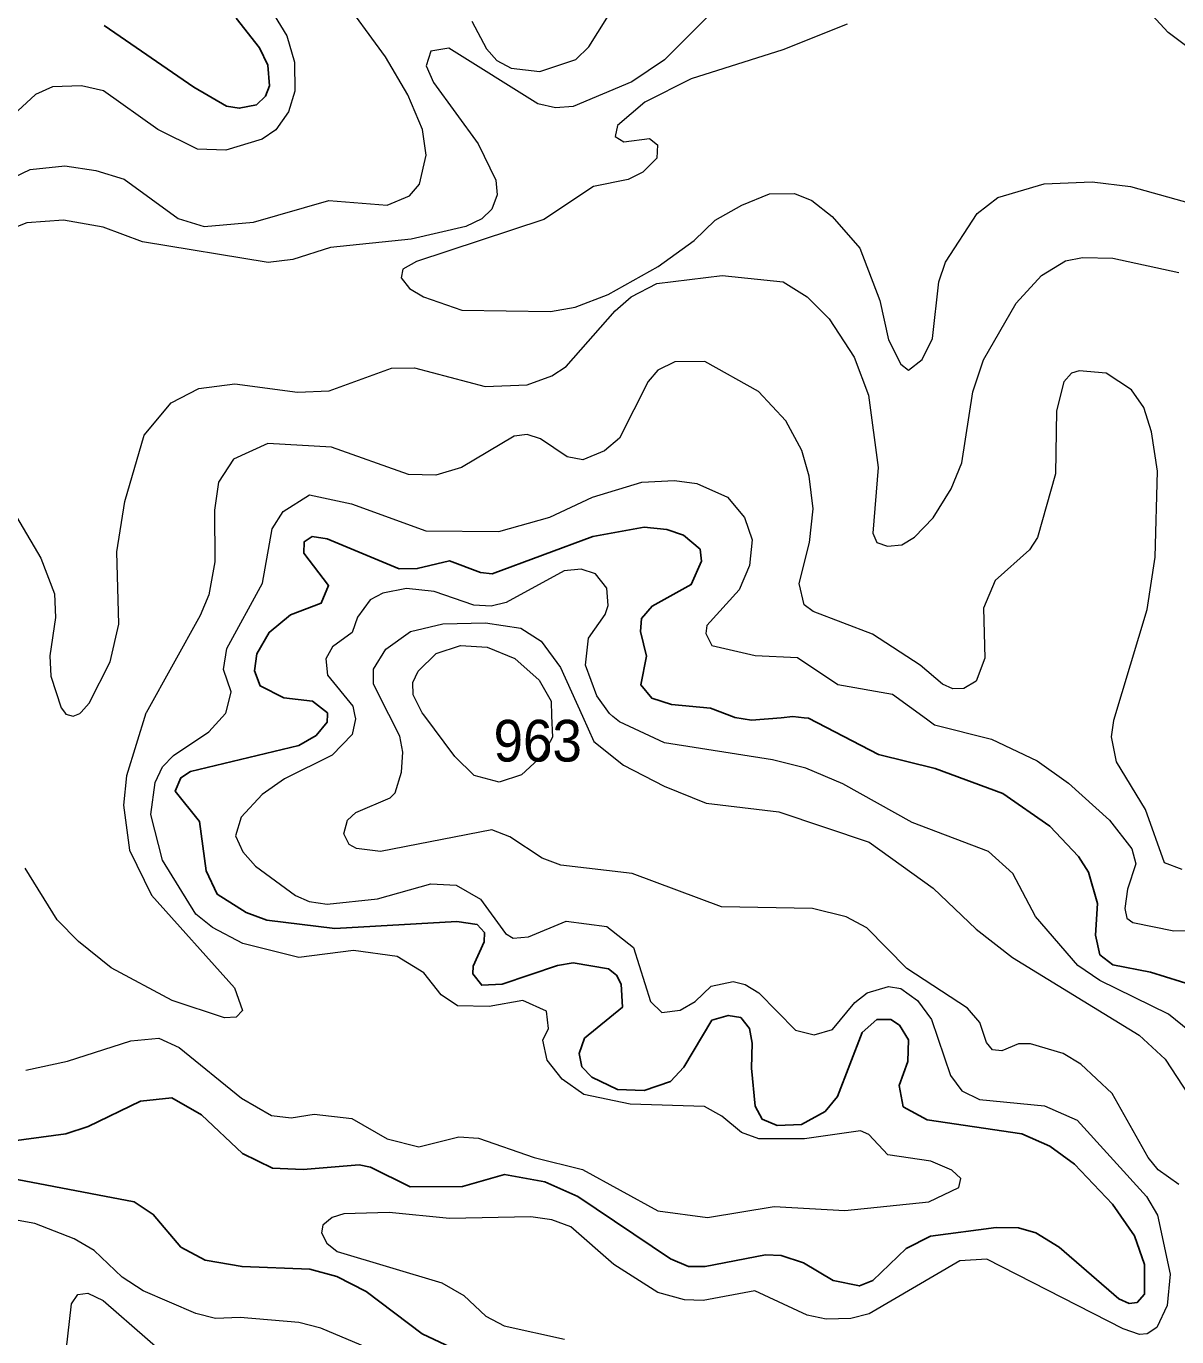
# Model space of a CAD drawing. Extents: x 473.9 to 500, y 7733.1 to 7760.8.
# Drawn here: x 487.667 to 489.876, y 7746.72 to 7749.235 of the extents above; entities that cross this region are included whole.
import ezdxf

# ---------------------------------------------------------------- set-up
doc = ezdxf.new("R2010")
doc.units = 0
doc.header["$LTSCALE"] = 0.032
doc.layers.add('1', color=7, linetype='Continuous', lineweight=25)
doc.layers.add('2', color=7, linetype='Continuous', lineweight=13)
doc.layers.add('21', color=7, linetype='Continuous')

msp = doc.modelspace()

# ---------------------------------------------------------------- linework, layer by layer
at = {"layer": '1'}
for points in [[(488.0704, 7749.25), (488.115, 7749.1932), (488.1315, 7749.16), (488.1344, 7749.1205), (488.1271, 7749.1005), (488.1098, 7749.084), (488.0764, 7749.0773), (488.052, 7749.0814), (487.9893, 7749.1176), (487.8171, 7749.2364)], [(488.2597, 7747.5034), (488.1295, 7747.5194), (488.09, 7747.5342), (488.0343, 7747.569), (488.0132, 7747.6137), (488.0001, 7747.7086), (487.9536, 7747.7668), (487.9642, 7747.7925), (487.9826, 7747.8046), (488.1908, 7747.8546), (488.2243, 7747.8739), (488.2451, 7747.899), (488.2455, 7747.9145), (488.2456, 7747.9168), (488.2167, 7747.9393), (488.1623, 7747.9461), (488.1163, 7747.9689), (488.1059, 7747.9974), (488.1101, 7748.0302), (488.134, 7748.0714), (488.1745, 7748.1053), (488.2338, 7748.1274), (488.2479, 7748.1614), (488.2003, 7748.2238), (488.2011, 7748.2455), (488.2166, 7748.2554), (488.2453, 7748.2511), (488.3836, 7748.1932), (488.4182, 7748.194), (488.4797, 7748.2087), (488.5398, 7748.1863), (488.5622, 7748.184), (488.755, 7748.2552), (488.8534, 7748.2732), (488.8974, 7748.2688), (488.9289, 7748.2583), (488.9614, 7748.2311), (488.9637, 7748.2083), (488.9441, 7748.1633), (488.8689, 7748.122), (488.8487, 7748.098), (488.8464, 7748.0734), (488.8584, 7748.0257), (488.8472, 7747.9706), (488.8683, 7747.945), (488.9064, 7747.9331), (488.9808, 7747.9259), (489.0262, 7747.9085), (489.0276, 7747.908), (489.0597, 7747.9028), (489.1168, 7747.9078), (489.139, 7747.9098), (489.1605, 7747.9075), (489.1689, 7747.9066), (489.3036, 7747.8372), (489.4123, 7747.8101), (489.5421, 7747.7621), (489.6326, 7747.6999), (489.6871, 7747.6415), (489.7064, 7747.6114), (489.7242, 7747.551), (489.7203, 7747.4905), (489.7286, 7747.4529), (489.7532, 7747.4337), (489.8256, 7747.4193), (489.9118, 7747.3922)], [(489.1596, 7746.8614), (489.2162, 7746.8274), (489.2669, 7746.8172), (489.2927, 7746.8277), (489.3563, 7746.8891), (489.403, 7746.913), (489.5291, 7746.9296), (489.5725, 7746.9289), (489.6057, 7746.9191), (489.6506, 7746.8915), (489.765, 7746.7922), (489.7848, 7746.7837), (489.8003, 7746.7855), (489.8143, 7746.8013), (489.814, 7746.8586), (489.7951, 7746.9133), (489.7525, 7746.9744), (489.6797, 7747.0507), (489.6324, 7747.0853), (489.5785, 7747.1088), (489.3968, 7747.1362), (489.3511, 7747.1612), (489.3432, 7747.2017), (489.3599, 7747.2481), (489.3608, 7747.2893), (489.3435, 7747.3174), (489.3269, 7747.3285), (489.3004, 7747.3288), (489.2721, 7747.3035), (489.225, 7747.1808), (489.2013, 7747.1522), (489.1554, 7747.1272), (489.1093, 7747.1248), (489.08, 7747.1373), (489.0669, 7747.1623), (489.0594, 7747.2352), (489.0613, 7747.2831), (489.056, 7747.3112), (489.0392, 7747.3322), (489.015, 7747.3364), (488.9836, 7747.3271), (488.9299, 7747.2369), (488.9041, 7747.2096), (488.8534, 7747.192), (488.8028, 7747.194), (488.7531, 7747.2176), (488.7342, 7747.238), (488.729, 7747.2636), (488.7391, 7747.2925), (488.8118, 7747.3519), (488.8097, 7747.3964), (488.8004, 7747.4136), (488.7853, 7747.4258), (488.7173, 7747.4372), (488.6872, 7747.4322), (488.5814, 7747.3965), (488.5419, 7747.3942), (488.5248, 7747.4165), (488.5255, 7747.4311), (488.5466, 7747.4777), (488.547, 7747.4957), (488.5331, 7747.5106), (488.4938, 7747.5166), (488.2597, 7747.5034)], [(487.6149, 7747.092), (487.7438, 7747.1092), (487.7866, 7747.1235), (487.8869, 7747.1719), (487.9468, 7747.1781), (488.004, 7747.1454), (488.0827, 7747.0713), (488.1405, 7747.0431), (488.1993, 7747.0407), (488.3066, 7747.0494), (488.3283, 7747.0449), (488.4042, 7747.0071), (488.5049, 7747.0082), (488.5858, 7747.031), (488.6627, 7747.0169), (488.7263, 7746.9888), (488.9043, 7746.8695), (488.9388, 7746.8542), (488.9705, 7746.8544), (489.0866, 7746.8766), (489.1167, 7746.8759), (489.1596, 7746.8614)], [(488.505, 7746.6889), (488.4277, 7746.725), (488.3199, 7746.8062), (488.2636, 7746.8351), (488.2121, 7746.8493), (488.0819, 7746.8542), (488.0107, 7746.8668), (487.9644, 7746.8914), (487.9112, 7746.9546), (487.8745, 7746.9789), (487.6368, 7747.0239)]]:
    msp.add_lwpolyline(points, dxfattribs=at)
at = {"layer": '2'}
for points in [[(490.0042, 7749.1272), (489.9516, 7749.1534), (489.8593, 7749.2228), (489.7146, 7749.381)], [(488.0844, 7749.3524), (488.1678, 7749.2162), (488.1823, 7749.166), (488.183, 7749.1102), (488.1708, 7749.0708), (488.1468, 7749.0362), (488.1206, 7749.0183), (488.0509, 7748.9967), (487.9961, 7748.9988), (487.9201, 7749.0363), (487.816, 7749.1107), (487.7737, 7749.1206), (487.7178, 7749.1184), (487.685, 7749.104), (487.6515, 7749.0725), (487.6157, 7749.0585), (487.4849, 7749.0582), (487.4608, 7749.0649), (487.3946, 7749.1045), (487.2779, 7749.2182), (487.2164, 7749.2396), (487.1231, 7749.2234), (487.0807, 7749.222), (486.9885, 7749.2429)], [(487.5798, 7748.9145), (487.6751, 7748.9597), (487.7416, 7748.967), (487.8011, 7748.9577), (487.8557, 7748.9412), (487.9589, 7748.8659), (488.009, 7748.8507), (488.1035, 7748.8588), (488.2481, 7748.9003), (488.3601, 7748.8912), (488.4032, 7748.9095), (488.4226, 7748.9318), (488.4354, 7748.9875), (488.428, 7749.0367), (488.4002, 7749.1032), (488.3574, 7749.1761), (488.2683, 7749.298)], [(488.523, 7749.2443), (488.5511, 7749.1913), (488.571, 7749.1693), (488.5981, 7749.1542), (488.6533, 7749.1481), (488.7226, 7749.1711), (488.7474, 7749.1952), (488.7992, 7749.2781)], [(488.9826, 7749.2602), (488.8927, 7749.1701), (488.8298, 7749.1284)], [(489.2435, 7749.2388), (489.1198, 7749.1893), (488.9441, 7749.134), (488.8549, 7749.0888), (488.8027, 7749.0441), (488.7981, 7749.023), (488.8145, 7749.0131), (488.8638, 7749.0191), (488.8793, 7749.007), (488.8781, 7748.9813), (488.8512, 7748.9547), (488.8227, 7748.9409), (488.7563, 7748.927), (488.6609, 7748.864), (488.4164, 7748.7835), (488.3901, 7748.7686), (488.3875, 7748.7519), (488.4033, 7748.7316), (488.4304, 7748.7152), (488.5038, 7748.6898), (488.6738, 7748.6873), (488.7215, 7748.6959), (488.7845, 7748.72), (488.8806, 7748.7738), (488.9496, 7748.8236), (488.9902, 7748.8624), (489.0409, 7748.8915), (489.0944, 7748.913), (489.1422, 7748.914), (489.1753, 7748.9005), (489.2145, 7748.8698), (489.2678, 7748.8089), (489.3062, 7748.7082), (489.3225, 7748.6327), (489.3464, 7748.5863), (489.3614, 7748.5749), (489.3871, 7748.5955), (489.4073, 7748.6353), (489.4194, 7748.7442), (489.4324, 7748.7823), (489.4928, 7748.8754), (489.5325, 7748.9064), (489.6214, 7748.9325), (489.7136, 7748.9365), (489.7875, 7748.9275), (489.9296, 7748.8877)], [(488.8298, 7749.1284), (488.7176, 7749.0805), (488.6835, 7749.0784), (488.6496, 7749.0856), (488.4786, 7749.1926), (488.4444, 7749.1869), (488.4355, 7749.1587), (488.4495, 7749.1267), (488.5349, 7749.0089), (488.569, 7748.9392), (488.5713, 7748.9114), (488.5613, 7748.884), (488.5419, 7748.8654), (488.5113, 7748.8504), (488.4063, 7748.8264), (488.2513, 7748.8103), (488.179, 7748.7871), (488.1319, 7748.7814), (487.8906, 7748.8211), (487.815, 7748.849), (487.739, 7748.8625), (487.6685, 7748.8572), (487.5893, 7748.826)], [(487.621, 7748.3399), (487.6954, 7748.2137), (487.7215, 7748.1454), (487.7239, 7748.1003), (487.7128, 7748.0263), (487.7148, 7747.9877), (487.7343, 7747.927), (487.7407, 7747.9184), (487.7436, 7747.9145), (487.7579, 7747.9108), (487.7706, 7747.9158), (487.7727, 7747.9181), (487.788, 7747.9356), (487.8283, 7748.0152), (487.8453, 7748.0875), (487.8414, 7748.2263), (487.8567, 7748.3227), (487.8942, 7748.4499), (487.9455, 7748.5123), (487.9989, 7748.5396), (488.068, 7748.5482), (488.1882, 7748.5322), (488.2489, 7748.5348), (488.3687, 7748.5787), (488.4128, 7748.5789), (488.5486, 7748.5437), (488.6292, 7748.5466), (488.6765, 7748.5637), (488.704, 7748.582), (488.7977, 7748.6884), (488.8287, 7748.7154), (488.8777, 7748.7409), (489.0032, 7748.7565), (489.1208, 7748.7444), (489.1663, 7748.7156), (489.2086, 7748.673), (489.2565, 7748.5999), (489.2844, 7748.527), (489.303, 7748.3882), (489.2927, 7748.2622), (489.3004, 7748.2441), (489.3207, 7748.2371), (489.348, 7748.2395), (489.3725, 7748.2543), (489.4082, 7748.2911), (489.4432, 7748.3469), (489.4632, 7748.3968), (489.4843, 7748.533), (489.5053, 7748.5946), (489.5677, 7748.7032), (489.6162, 7748.7566), (489.6627, 7748.7843), (489.6948, 7748.791), (489.7533, 7748.7894), (489.8803, 7748.762)], [(489.8861, 7747.6165), (489.8522, 7747.6289), (489.8162, 7747.7316), (489.7606, 7747.8228), (489.7509, 7747.8708), (489.7554, 7747.9025), (489.7555, 7747.9029), (489.8192, 7748.1154), (489.8344, 7748.2161), (489.8393, 7748.3812), (489.8275, 7748.4562), (489.8129, 7748.5034), (489.7892, 7748.537), (489.7404, 7748.5691), (489.6884, 7748.5737), (489.6742, 7748.5691), (489.6593, 7748.5521), (489.6449, 7748.4965), (489.6431, 7748.3759), (489.6085, 7748.2533), (489.5931, 7748.2301), (489.5274, 7748.1712), (489.5049, 7748.118), (489.5077, 7748.022), (489.4908, 7747.9777), (489.4674, 7747.964), (489.4463, 7747.9629), (489.4265, 7747.9718), (489.3834, 7748.0087), (489.2917, 7748.0682), (489.1778, 7748.1117), (489.1607, 7748.1243), (489.1509, 7748.1651), (489.1709, 7748.2439), (489.1784, 7748.3089), (489.1702, 7748.3711), (489.1563, 7748.4208), (489.1253, 7748.4772), (489.073, 7748.5336), (488.9701, 7748.5916), (488.9127, 7748.5906), (488.8802, 7748.5747), (488.8615, 7748.5532), (488.8066, 7748.4443), (488.7778, 7748.4197), (488.7361, 7748.4028), (488.706, 7748.4087), (488.6549, 7748.4428), (488.6291, 7748.451), (488.6043, 7748.4482), (488.5033, 7748.388)], [(488.5033, 7748.388), (488.4538, 7748.373), (488.4015, 7748.3744), (488.2537, 7748.4267), (488.1313, 7748.434), (488.0655, 7748.4039), (488.0363, 7748.3597), (488.0287, 7748.3058), (488.0296, 7748.2068), (488.0178, 7748.1438), (488.0013, 7748.1036), (487.8977, 7747.9172), (487.8973, 7747.9164), (487.8597, 7747.7962), (487.8541, 7747.74), (487.8657, 7747.6535), (487.908, 7747.5673), (488.0671, 7747.3896), (488.0828, 7747.3457), (488.0706, 7747.333), (488.0482, 7747.3319), (487.9475, 7747.3647), (487.8308, 7747.4275), (487.7679, 7747.4781), (487.7271, 7747.5199), (487.6654, 7747.6189)], [(487.6666, 7747.2314), (487.747, 7747.2487), (487.8681, 7747.2874), (487.9223, 7747.293), (487.9611, 7747.2746), (488.081, 7747.1775), (488.1383, 7747.1446), (488.1763, 7747.1395), (488.2203, 7747.1467), (488.2926, 7747.1387), (488.3606, 7747.0996), (488.4213, 7747.0842), (488.4982, 7747.1032), (488.5354, 7747.1007), (488.6426, 7747.0636), (488.7353, 7747.0406), (488.8799, 7746.9612), (488.9755, 7746.9483), (489.1031, 7746.9699), (489.239, 7746.9618), (489.4001, 7746.9784), (489.4576, 7747.006), (489.4615, 7747.0237), (489.4443, 7747.0392), (489.4042, 7747.0567), (489.3214, 7747.069), (489.2852, 7747.1081), (489.2692, 7747.115), (489.1615, 7747.0994), (489.0741, 7747.0992), (489.0404, 7747.1118), (489.0026, 7747.1432), (488.9695, 7747.1615), (488.827, 7747.1663), (488.738, 7747.1844), (488.6963, 7747.2139), (488.6675, 7747.2502), (488.659, 7747.2891), (488.67, 7747.311), (488.6662, 7747.3448), (488.6209, 7747.3647), (488.5562, 7747.3537), (488.4952, 7747.3545), (488.4642, 7747.376), (488.4305, 7747.4184), (488.3795, 7747.4494), (488.2958, 7747.461), (488.1908, 7747.4476), (488.083, 7747.4741), (488.025, 7747.5048), (487.9928, 7747.5308), (487.9288, 7747.6345), (487.9066, 7747.7221), (487.9147, 7747.7836), (487.9293, 7747.8137), (487.9502, 7747.8355), (488.018, 7747.8807), (488.0497, 7747.916), (488.0516, 7747.9181), (488.0609, 7747.9572), (488.0464, 7748.0002), (488.0528, 7748.0408), (488.1211, 7748.1658), (488.1393, 7748.2703), (488.161, 7748.3033), (488.2114, 7748.3357), (488.2921, 7748.318), (488.4346, 7748.2661), (488.5745, 7748.2652), (488.6726, 7748.2926), (488.7546, 7748.3308), (488.849, 7748.3599), (488.9117, 7748.3633), (488.9546, 7748.3575), (489.0135, 7748.3309), (489.0465, 7748.2917), (489.0609, 7748.2489), (489.0561, 7748.2), (489.036, 7748.1533), (488.9742, 7748.0848), (488.9723, 7748.0693), (488.9836, 7748.0466), (489.0666, 7748.0273), (489.148, 7748.0234), (489.2253, 7747.9712), (489.3303, 7747.9532), (489.3955, 7747.9057), (489.4113, 7747.8942), (489.5201, 7747.8663), (489.6083, 7747.8252), (489.668, 7747.7819), (489.7467, 7747.7112), (489.7896, 7747.6561), (489.7974, 7747.6276)], [(488.7934, 7747.9103), (488.7872, 7747.9155), (488.7628, 7747.9497), (488.7413, 7748.0084), (488.7466, 7748.0605), (488.7789, 7748.1058), (488.7844, 7748.1234), (488.7818, 7748.1563), (488.7601, 7748.1836), (488.7327, 7748.1927), (488.7001, 7748.1896), (488.5887, 7748.1288), (488.5603, 7748.1217), (488.5269, 7748.1235), (488.4507, 7748.1501), (488.3976, 7748.1557), (488.352, 7748.147), (488.3278, 7748.1341), (488.3031, 7748.1009), (488.2931, 7748.0715), (488.2557, 7748.0436), (488.2424, 7748.0205), (488.2458, 7747.9892), (488.2947, 7747.9299), (488.2978, 7747.9141), (488.2996, 7747.9053), (488.2932, 7747.8752), (488.2548, 7747.8358), (488.1634, 7747.7903), (488.1203, 7747.7603), (488.0799, 7747.7169), (488.0691, 7747.6809), (488.0831, 7747.6504), (488.1078, 7747.6225), (488.1844, 7747.5662), (488.2106, 7747.555), (488.2454, 7747.55), (488.3419, 7747.5602), (488.4443, 7747.589), (488.493, 7747.5864), (488.5395, 7747.5596), (488.5872, 7747.4938), (488.602, 7747.4848), (488.6319, 7747.487), (488.7038, 7747.5174), (488.7823, 7747.5073), (488.8333, 7747.4668), (488.8659, 7747.3634), (488.8875, 7747.3419), (488.9229, 7747.3466), (488.9517, 7747.3629), (488.982, 7747.3922), (489.0243, 7747.4017), (489.0474, 7747.3959), (489.0735, 7747.3796), (489.1444, 7747.3081), (489.1802, 7747.2991), (489.2154, 7747.3096), (489.258, 7747.3614), (489.2816, 7747.3796), (489.3229, 7747.3921), (489.3463, 7747.388), (489.3785, 7747.3647), (489.4051, 7747.3285), (489.4417, 7747.2213), (489.4635, 7747.1914), (489.4975, 7747.1751), (489.6221, 7747.1631), (489.685, 7747.1356), (489.818, 7746.9888), (489.839, 7746.9527), (489.8634, 7746.8396), (489.8576, 7746.7794), (489.8375, 7746.7376), (489.8191, 7746.7253), (489.8047, 7746.7238), (489.773, 7746.7348), (489.5116, 7746.8687), (489.4598, 7746.8653), (489.2853, 7746.7634), (489.2505, 7746.7549), (489.2033, 7746.7537), (489.1663, 7746.7609), (489.0661, 7746.8075), (488.9669, 7746.789), (488.931, 7746.7905), (488.8802, 7746.8044), (488.7956, 7746.8585), (488.7132, 7746.9305), (488.6764, 7746.9439), (488.6362, 7746.9499), (488.4797, 7746.9467), (488.3644, 7746.9579), (488.2771, 7746.9553), (488.2549, 7746.9484), (488.2369, 7746.934), (488.2346, 7746.919), (488.2447, 7746.8995), (488.2641, 7746.8831), (488.4653, 7746.8234)], [(489.8798, 7747.012), (489.8405, 7747.0403), (489.8211, 7747.0637), (489.7519, 7747.1865), (489.6916, 7747.2427), (489.6578, 7747.2635), (489.5953, 7747.2819), (489.5722, 7747.2819), (489.5404, 7747.2683), (489.5223, 7747.2702), (489.5111, 7747.2841), (489.498, 7747.3225), (489.4742, 7747.3502), (489.3581, 7747.4262), (489.2809, 7747.5043), (489.2414, 7747.5256), (489.1765, 7747.5414), (489.0023, 7747.5448), (488.8307, 7747.6086), (488.6937, 7747.6245), (488.6577, 7747.6383), (488.5957, 7747.6793), (488.5611, 7747.6927), (488.3473, 7747.6511), (488.3014, 7747.657), (488.2871, 7747.6647), (488.2774, 7747.685), (488.284, 7747.7113), (488.2999, 7747.7257), (488.3662, 7747.7539), (488.376, 7747.7633), (488.3881, 7747.8034), (488.3904, 7747.8414), (488.3844, 7747.8725), (488.3637, 7747.9136), (488.3341, 7747.9723), (488.3343, 7748.0006), (488.3578, 7748.0392), (488.4052, 7748.0735), (488.4672, 7748.0876), (488.5488, 7748.0899), (488.6168, 7748.0797), (488.656, 7748.0548), (488.6933, 7748.0038), (488.7351, 7747.9108), (488.7571, 7747.8619), (488.8142, 7747.8166), (488.892, 7747.7761), (488.9728, 7747.7437), (489.1122, 7747.7272), (489.2853, 7747.6686), (489.4085, 7747.5809), (489.4909, 7747.5022), (489.5605, 7747.4476), (489.8041, 7747.2987), (489.8541, 7747.2526), (489.8987, 7747.1838)], [(489.0999, 7747.8271), (488.8924, 7747.8597), (488.8064, 7747.8995), (488.7934, 7747.9103)], [(489.9374, 7747.2763), (489.86, 7747.3388), (489.7285, 7747.4035), (489.6862, 7747.4319), (489.6048, 7747.5265), (489.5615, 7747.6088), (489.5147, 7747.6512), (489.3683, 7747.7069), (489.2349, 7747.7806), (489.1642, 7747.8111), (489.0999, 7747.8271)], [(489.7974, 7747.6276), (489.7812, 7747.5788), (489.7765, 7747.5418), (489.7803, 7747.5231), (489.7917, 7747.5147), (489.8701, 7747.499), (489.9193, 7747.4992)], [(488.3467, 7746.6882), (488.2331, 7746.736), (488.1907, 7746.747), (488.0784, 7746.7567), (488.0305, 7746.7545), (487.9928, 7746.764), (487.892, 7746.8075), (487.8518, 7746.8343), (487.7978, 7746.8849), (487.7593, 7746.9076), (487.6837, 7746.9369), (487.6378, 7746.9456)], [(488.4653, 7746.8234), (488.5075, 7746.7991), (488.55, 7746.7589), (488.5847, 7746.7408), (488.7005, 7746.7148)], [(487.7408, 7746.6644), (487.7543, 7746.7831), (487.7666, 7746.8009), (487.7855, 7746.8031), (487.8155, 7746.789), (488.0702, 7746.5663)]]:
    msp.add_lwpolyline(points, dxfattribs=at)
msp.add_lwpolyline([(488.6185, 7747.7979), (488.5754, 7747.7842), (488.5271, 7747.7967), (488.4901, 7747.8335), (488.431, 7747.9131), (488.4278, 7747.9174), (488.41, 7747.9517), (488.4097, 7747.9754), (488.42, 7747.997), (488.4544, 7748.0307), (488.5012, 7748.0466), (488.5526, 7748.0431), (488.6056, 7748.0212), (488.6521, 7747.98), (488.6749, 7747.9395), (488.676, 7747.9112), (488.6776, 7747.8704), (488.6589, 7747.8359)], close=True, dxfattribs=at)

# ---------------------------------------------------------------- texts
at = {"layer": '21', "width": 0.95}
msp.add_text('963', height=0.08, dxfattribs=at).set_placement((488.5646, 7747.8236))

doc.saveas('drawing.dxf')
